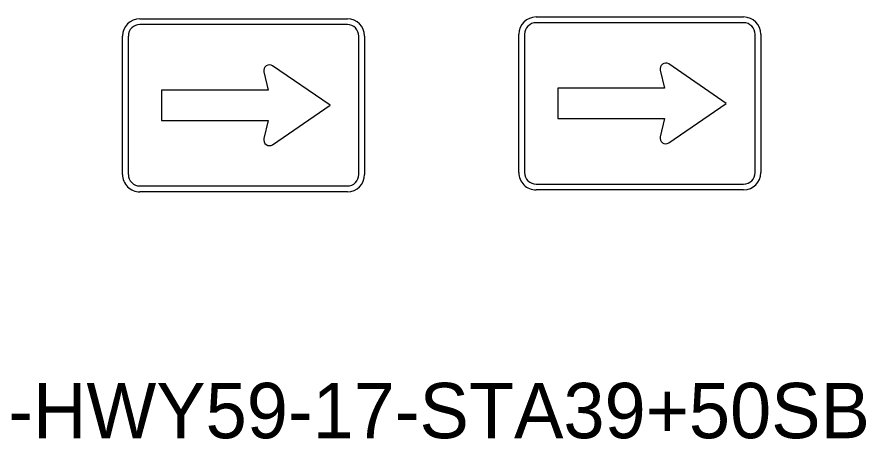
# Model space of a CAD drawing. Extents: x 620856.8 to 620948.6, y 415598.8 to 415658.2.
# Drawn here: x 620899.13 to 620905.27, y 415634.39 to 415637.44 of the extents above; entities that cross this region are included whole.
import ezdxf

# ---------------------------------------------------------------- set-up
doc = ezdxf.new("R2010")
doc.units = 0
doc.layers.add('SIGNS', color=7, linetype='Continuous')

msp = doc.modelspace()

# ---------------------------------------------------------------- linework, layer by layer
at = {"layer": 'SIGNS'}
for p, q in [((620900.0172, 415637.4316), (620901.5172, 415637.4316)), ((620901.5172, 415637.4316), (620901.5172, 415637.4316)), ((620902.8818, 415637.4448), (620904.3818, 415637.4448)), ((620904.3818, 415637.4031), (620902.8818, 415637.4031)), ((620904.3818, 415637.4448), (620904.3818, 415637.4448)), ((620901.5172, 415637.39), (620900.0172, 415637.39)), ((620899.8922, 415636.3066), (620899.8922, 415637.3066)), ((620899.9338, 415637.3066), (620899.9338, 415636.3066)), ((620901.6005, 415636.3066), (620901.6005, 415637.3066)), ((620901.6422, 415637.3066), (620901.6422, 415636.3066)), ((620902.7568, 415636.3198), (620902.7568, 415637.3198)), ((620902.7984, 415637.3198), (620902.7984, 415636.3198)), ((620904.4651, 415636.3198), (620904.4651, 415637.3198)), ((620904.5068, 415637.3198), (620904.5068, 415636.3198)), ((620901.3922, 415636.8066), (620900.9769, 415637.0919)), ((620904.2568, 415636.8198), (620903.8415, 415637.105)), ((620900.9141, 415637.0473), (620900.9442, 415636.916)), ((620903.7787, 415637.0605), (620903.8089, 415636.9292)), ((620900.9442, 415636.916), (620900.1734, 415636.916)), ((620900.1734, 415636.916), (620900.1734, 415636.6973)), ((620903.8089, 415636.9292), (620903.038, 415636.9292)), ((620903.038, 415636.9292), (620903.038, 415636.7104)), ((620900.9769, 415636.5214), (620901.3922, 415636.8066)), ((620903.8415, 415636.5346), (620904.2568, 415636.8198)), ((620900.1734, 415636.6973), (620900.9442, 415636.6973)), ((620900.9442, 415636.6973), (620900.9141, 415636.566)), ((620903.038, 415636.7104), (620903.8089, 415636.7104)), ((620903.8089, 415636.7104), (620903.7787, 415636.5791)), ((620902.8818, 415636.2365), (620904.3818, 415636.2365)), ((620900.0172, 415636.2233), (620901.5172, 415636.2233)), ((620901.5172, 415636.1816), (620900.0172, 415636.1816)), ((620900.0172, 415636.1816), (620900.0172, 415636.1816)), ((620904.3818, 415636.1948), (620902.8818, 415636.1948)), ((620902.8818, 415636.1948), (620902.8818, 415636.1948))]:
    msp.add_line(p, q, dxfattribs=at)
for points in [[(620900.0172, 415637.4316), (620900.0172, 415637.4316)], [(620902.8818, 415637.4448), (620902.8818, 415637.4448)], [(620899.8922, 415637.3066), (620899.8922, 415637.3066)], [(620902.7568, 415637.3198), (620902.7568, 415637.3198)], [(620901.6422, 415636.3066), (620901.6422, 415636.3066)], [(620904.5068, 415636.3198), (620904.5068, 415636.3198)], [(620901.5172, 415636.1816), (620901.5172, 415636.1816)], [(620904.3818, 415636.1948), (620904.3818, 415636.1948)]]:
    msp.add_lwpolyline(points, dxfattribs=at)
for centre, radius, start, end in [((620900.0172, 415637.3066), 0.125, 90.00021, 179.99985), ((620901.5172, 415637.3066), 0.125, 0, 90), ((620902.8818, 415637.3198), 0.125, 90.00021, 179.99985), ((620902.8818, 415637.3198), 0.0833, 90.00021, 179.99985), ((620904.3818, 415637.3198), 0.125, 0, 90), ((620904.3818, 415637.3198), 0.0833, 0, 90.00021), ((620900.0172, 415637.3066), 0.0833, 90.00021, 179.99985), ((620901.5172, 415637.3066), 0.0833, 0, 90.00021), ((620900.9547, 415637.0566), 0.0417, 57.72435, 192.95041), ((620903.8193, 415637.0698), 0.0417, 57.72435, 192.95041), ((620900.9547, 415636.5566), 0.0417, 167.04986, 302.27592), ((620903.8193, 415636.5698), 0.0417, 167.04986, 302.27592), ((620900.0172, 415636.3066), 0.125, 179.99985, 270), ((620900.0172, 415636.3066), 0.0833, 179.99985, 270.00006), ((620901.5172, 415636.3066), 0.125, 270.00006, 360), ((620901.5172, 415636.3066), 0.0833, 270.00006, 0.00027), ((620902.8818, 415636.3198), 0.125, 179.99985, 270), ((620902.8818, 415636.3198), 0.0833, 179.99985, 270.00006), ((620904.3818, 415636.3198), 0.125, 270.00006, 360), ((620904.3818, 415636.3198), 0.0833, 270.00006, 0.00027)]:
    msp.add_arc(centre, radius, start, end, dxfattribs=at)

# ---------------------------------------------------------------- texts
msp.add_text('SS-HWY59-17-STA39+50SB', height=0.4, rotation=0, dxfattribs=at).set_placement((620898.3531, 415634.4001))

doc.saveas('drawing.dxf')
